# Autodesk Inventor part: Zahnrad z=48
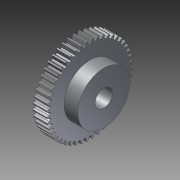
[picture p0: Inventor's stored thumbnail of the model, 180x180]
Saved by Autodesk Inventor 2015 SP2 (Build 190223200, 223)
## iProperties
Created: 2012-07
Part Number: Zahnrad z=48
Material: Stahl
Document SubType Name: Modeling
Designer: rYan
Mass: 18.3991 g
Surface Area: 17.4108 cm^2
Volume: 2.34384 cm^3
Density: 7.85 g/cm^3
Appearance: Platte
Übersetzungsnorm: STEP AP214IS
Dateiname: c:/PPEXPORT/antriebselemente_und_normteile/stirnzahnraeder/stirnzahnraeder_stahl/modul_05_und_07/artikel_nr___21104800.stp
Postprozessor: Build: 138, Release: 2013 RTM - Date: Thu 03/01/2012
Gesendete Einheiten: Millimeter
Unbestimmtheit: 1.0000000000000002e-06
Author: rYan
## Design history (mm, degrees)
node "11"
node "1"
node "Basis1"
